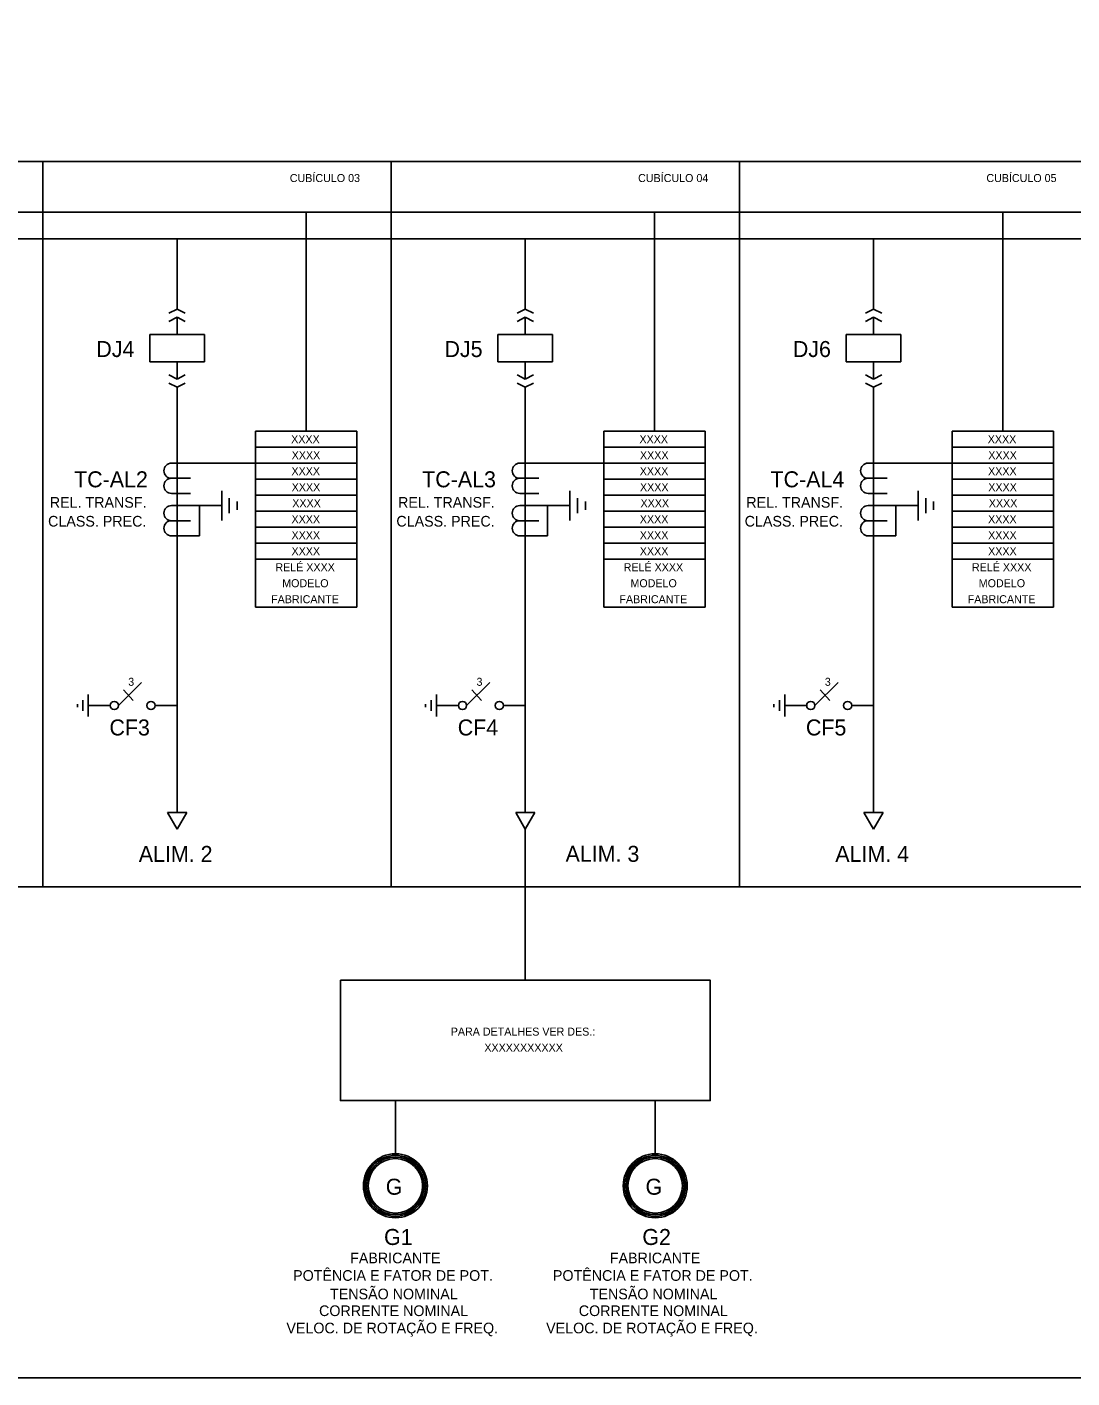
# Model space of a CAD drawing. Extents: x 563 to 1404, y 358 to 952.
# Drawn here: x 837 to 1032.8, y 494.9 to 748.2 of the extents above; entities that cross this region are included whole.
import ezdxf

# ---------------------------------------------------------------- set-up
doc = ezdxf.new("R2010")
doc.units = 0
doc.layers.add('13', color=7, linetype='Continuous')
doc.layers.add('New Level (0)', color=7, linetype='Continuous')

msp = doc.modelspace()

# ---------------------------------------------------------------- linework, layer by layer
for p, q in [((1296.89, 722.95), (622.37, 722.95)), ((839.94, 722.95), (839.94, 586.96)), ((839.94, 722.95), (839.94, 586.96)), ((905.22, 722.95), (905.22, 586.96)), ((905.22, 722.95), (905.22, 586.96)), ((970.5, 722.95), (970.5, 586.96)), ((970.5, 722.95), (970.5, 586.96)), ((1280.96, 713.45), (705.72, 713.45)), ((889.29, 672.38), (889.29, 713.45)), ((954.57, 672.38), (954.57, 713.45)), ((1019.85, 672.38), (1019.85, 713.45)), ((1256.75, 708.46), (681.52, 708.46)), ((865.09, 695.25), (865.09, 708.46)), ((865.09, 695.25), (865.09, 708.46)), ((930.37, 695.25), (930.37, 708.46)), ((930.37, 695.25), (930.37, 708.46)), ((995.64, 695.25), (995.64, 708.46)), ((995.64, 695.25), (995.64, 708.46)), ((865.09, 690.5), (865.09, 693.73)), ((865.09, 690.5), (865.09, 693.73)), ((930.37, 690.5), (930.37, 693.73)), ((930.37, 690.5), (930.37, 693.73)), ((995.64, 690.5), (995.64, 693.73)), ((995.64, 690.5), (995.64, 693.73)), ((859.97, 685.38), (859.97, 690.5)), ((859.97, 690.5), (870.21, 690.5)), ((870.21, 690.5), (870.21, 685.38)), ((925.24, 685.38), (925.24, 690.5)), ((925.24, 690.5), (935.49, 690.5)), ((935.49, 690.5), (935.49, 685.38)), ((990.52, 690.5), (1000.76, 690.5)), ((990.52, 685.38), (990.52, 690.5)), ((1000.76, 690.5), (1000.76, 685.38)), ((870.21, 685.38), (859.97, 685.38)), ((865.09, 685.38), (865.09, 682.16)), ((935.49, 685.38), (925.24, 685.38)), ((930.37, 685.38), (930.37, 682.16)), ((1000.76, 685.38), (990.52, 685.38)), ((995.64, 685.38), (995.64, 682.16)), ((865.09, 600.87), (865.09, 680.63)), ((930.37, 600.87), (930.37, 680.63)), ((995.64, 600.87), (995.64, 680.63)), ((898.78, 672.38), (879.8, 672.38)), ((879.8, 672.38), (879.8, 639.38)), ((898.78, 672.38), (898.78, 639.38)), ((964.06, 672.38), (945.08, 672.38)), ((945.08, 672.38), (945.08, 639.38)), ((964.06, 672.38), (964.06, 639.38)), ((1029.34, 672.38), (1010.36, 672.38)), ((1010.36, 672.38), (1010.36, 639.38)), ((1029.34, 672.38), (1029.34, 639.38)), ((898.78, 669.38), (879.8, 669.38)), ((964.06, 669.38), (945.08, 669.38)), ((1029.34, 669.38), (1010.36, 669.38)), ((864.06, 666.38), (867.6, 666.38)), ((879.8, 666.38), (867.6, 666.38)), ((898.78, 666.38), (879.8, 666.38)), ((929.34, 666.38), (932.88, 666.38)), ((945.08, 666.38), (932.88, 666.38)), ((964.06, 666.38), (945.08, 666.38)), ((994.62, 666.38), (998.16, 666.38)), ((1010.36, 666.38), (998.16, 666.38)), ((1029.34, 666.38), (1010.36, 666.38)), ((864.06, 663.55), (867.6, 663.55)), ((873.47, 661.21), (873.47, 655.63)), ((898.78, 663.38), (879.8, 663.38)), ((929.34, 663.55), (932.88, 663.55)), ((938.74, 661.21), (938.74, 655.63)), ((964.06, 663.38), (945.08, 663.38)), ((994.62, 663.55), (998.16, 663.55)), ((1004.02, 661.21), (1004.02, 655.63)), ((1029.34, 663.38), (1010.36, 663.38)), ((864.06, 660.72), (867.6, 660.72)), ((874.86, 657.02), (874.86, 659.82)), ((876.34, 659.2), (876.34, 657.64)), ((898.78, 660.38), (879.8, 660.38)), ((929.34, 660.72), (932.88, 660.72)), ((940.14, 657.02), (940.14, 659.82)), ((941.62, 659.2), (941.62, 657.64)), ((964.06, 660.38), (945.08, 660.38)), ((994.62, 660.72), (998.16, 660.72)), ((1005.42, 657.02), (1005.42, 659.82)), ((1006.9, 659.2), (1006.9, 657.64)), ((1029.34, 660.38), (1010.36, 660.38)), ((864.06, 658.42), (867.6, 658.42)), ((865.09, 658.42), (873.47, 658.42)), ((898.78, 657.38), (879.8, 657.38)), ((929.34, 658.42), (932.88, 658.42)), ((930.37, 658.42), (938.74, 658.42)), ((964.06, 657.38), (945.08, 657.38)), ((994.62, 658.42), (998.16, 658.42)), ((995.64, 658.42), (1004.02, 658.42)), ((1029.34, 657.38), (1010.36, 657.38)), ((864.06, 655.59), (867.6, 655.59)), ((898.78, 654.38), (879.8, 654.38)), ((898.78, 654.38), (879.8, 654.38)), ((929.34, 655.59), (932.88, 655.59)), ((964.06, 654.38), (945.08, 654.38)), ((964.06, 654.38), (945.08, 654.38)), ((994.62, 655.59), (998.16, 655.59)), ((1029.34, 654.38), (1010.36, 654.38)), ((1029.34, 654.38), (1010.36, 654.38)), ((864.06, 652.76), (869.28, 652.76)), ((898.78, 651.38), (879.8, 651.38)), ((929.34, 652.76), (934.55, 652.76)), ((964.06, 651.38), (945.08, 651.38)), ((994.62, 652.76), (999.83, 652.76)), ((1029.34, 651.38), (1010.36, 651.38)), ((898.78, 648.38), (879.8, 648.38)), ((964.06, 648.38), (945.08, 648.38)), ((1029.34, 648.38), (1010.36, 648.38)), ((898.78, 639.38), (879.8, 639.38)), ((964.06, 639.38), (945.08, 639.38)), ((1029.34, 639.38), (1010.36, 639.38)), ((858.43, 625.29), (854.09, 620.95)), ((855.08, 623.9), (856.87, 621.88)), ((923.7, 625.29), (919.36, 620.95)), ((920.35, 623.9), (922.15, 621.88)), ((988.98, 625.29), (984.64, 620.95)), ((985.63, 623.9), (987.43, 621.88)), ((846.41, 621.19), (846.41, 620.66)), ((847.43, 619.93), (847.43, 621.98)), ((848.45, 623), (848.45, 618.91)), ((852.55, 620.95), (848.45, 620.95)), ((865.09, 620.95), (860.99, 620.95)), ((911.69, 621.19), (911.69, 620.66)), ((912.71, 619.93), (912.71, 621.98)), ((913.73, 623), (913.73, 618.91)), ((917.83, 620.95), (913.73, 620.95)), ((930.37, 620.95), (926.27, 620.95)), ((976.97, 621.19), (976.97, 620.66)), ((977.98, 619.93), (977.98, 621.98)), ((979.01, 623), (979.01, 618.91)), ((983.1, 620.95), (979.01, 620.95)), ((995.64, 620.95), (991.55, 620.95)), ((866.9, 600.87), (863.28, 600.87)), ((863.28, 600.87), (865.09, 597.77)), ((866.9, 600.87), (863.28, 600.87)), ((865.09, 597.77), (866.9, 600.87)), ((932.18, 600.87), (928.56, 600.87)), ((932.18, 600.87), (928.56, 600.87)), ((928.56, 600.87), (930.37, 597.77)), ((930.37, 597.77), (932.18, 600.87)), ((997.45, 600.87), (993.83, 600.87)), ((993.83, 600.87), (995.64, 597.77)), ((997.45, 600.87), (993.83, 600.87)), ((995.64, 597.77), (997.45, 600.87)), ((930.37, 569.44), (930.37, 597.77)), ((1296.89, 586.96), (622.37, 586.96))]:
    msp.add_line(p, q)
for points in [[(906.02, 536.91), (906.02, 546.88)], [(954.71, 536.91), (954.71, 546.88)]]:
    msp.add_lwpolyline(points)
for centre, radius in [((853.32, 620.95), 0.768), ((860.22, 620.95), 0.768), ((918.6, 620.95), 0.768), ((925.5, 620.95), 0.768), ((983.87, 620.95), 0.768), ((990.78, 620.95), 0.768), ((906.02, 530.91), 6), ((906.02, 530.91), 5.7), ((906.02, 530.91), 5.4), ((906.02, 530.91), 5.1), ((954.71, 530.91), 6), ((954.71, 530.91), 5.7), ((954.71, 530.91), 5.4), ((954.71, 530.91), 5.1)]:
    msp.add_circle(centre, radius)
for centre in [(864.06, 664.97), (929.34, 664.97), (994.62, 664.97), (864.06, 662.14), (929.34, 662.14), (994.62, 662.14), (864.06, 657.01), (929.34, 657.01), (994.62, 657.01), (864.06, 654.18), (929.34, 654.18), (994.62, 654.18)]:
    msp.add_arc(centre, 1.42, 90, 270)
at = {"layer": '13'}
for p, q in [((865.09, 695.25), (863.56, 694.49)), ((865.09, 695.25), (866.61, 694.49)), ((930.37, 695.25), (928.84, 694.49)), ((930.37, 695.25), (931.89, 694.49)), ((995.64, 695.25), (994.12, 694.49)), ((995.64, 695.25), (997.17, 694.49)), ((865.09, 693.73), (863.56, 692.97)), ((865.09, 693.73), (866.61, 692.97)), ((930.37, 693.73), (928.84, 692.97)), ((930.37, 693.73), (931.89, 692.97)), ((995.64, 693.73), (994.12, 692.97)), ((995.64, 693.73), (997.17, 692.97)), ((865.09, 682.16), (863.56, 682.92)), ((865.09, 680.63), (863.56, 681.4)), ((865.09, 682.16), (866.61, 682.92)), ((865.09, 680.63), (866.61, 681.4)), ((930.37, 682.16), (928.84, 682.92)), ((930.37, 680.63), (928.84, 681.4)), ((930.37, 682.16), (931.89, 682.92)), ((930.37, 680.63), (931.89, 681.4)), ((995.64, 682.16), (994.12, 682.92)), ((995.64, 680.63), (994.12, 681.4)), ((995.64, 682.16), (997.17, 682.92)), ((995.64, 680.63), (997.17, 681.4))]:
    msp.add_line(p, q, dxfattribs=at)
at = {"layer": 'New Level (0)'}
for p, q in [((869.28, 658.42), (869.28, 652.76)), ((934.55, 658.42), (934.55, 652.76)), ((999.83, 658.42), (999.83, 652.76))]:
    msp.add_line(p, q, dxfattribs=at)
for points in [[(592.61, 760.21), (1379.09, 760.21), (1379.09, 494.89), (592.61, 494.89)], [(895.7, 569.44), (965.03, 569.44), (965.03, 546.88), (895.7, 546.88)]]:
    msp.add_lwpolyline(points, close=True, dxfattribs=at)

# ---------------------------------------------------------------- texts
for s, height, p in [('CUBÍCULO 03', 1.5, (886.23, 719.09)), ('CUBÍCULO 04', 1.5, (951.51, 719.09)), ('CUBÍCULO 05', 1.5, (1016.78, 719.09)), ('DJ4', 3, (849.96, 686.28)), ('DJ5', 3, (915.22, 686.28)), ('DJ6', 3, (980.51, 686.28)), ('XXXX', 1.5, (886.48, 670.13)), ('XXXX', 1.5, (951.76, 670.13)), ('XXXX', 1.5, (1017.04, 670.13)), ('XXXX', 1.5, (886.58, 667.13)), ('XXXX', 1.5, (951.86, 667.13)), ('XXXX', 1.5, (1017.14, 667.13)), ('TC-AL2', 3, (845.8, 661.86)), ('XXXX', 1.5, (886.54, 664.13)), ('TC-AL3', 3, (911.04, 661.86)), ('XXXX', 1.5, (951.82, 664.13)), ('TC-AL4', 3, (976.33, 661.86)), ('XXXX', 1.5, (1017.1, 664.13)), ('XXXX', 1.5, (886.58, 661.13)), ('XXXX', 1.5, (951.86, 661.13)), ('XXXX', 1.5, (1017.14, 661.13)), ('REL. TRANSF.', 2, (841.24, 658.04)), ('XXXX', 1.5, (886.69, 658.13)), ('REL. TRANSF.', 2, (906.51, 658.04)), ('XXXX', 1.5, (951.96, 658.13)), ('REL. TRANSF.', 2, (971.79, 658.04)), ('XXXX', 1.5, (1017.24, 658.13)), ('CLASS. PREC.', 2, (840.92, 654.5)), ('XXXX', 1.5, (886.55, 655.13)), ('CLASS. PREC.', 2, (906.2, 654.5)), ('XXXX', 1.5, (951.83, 655.13)), ('CLASS. PREC.', 2, (971.48, 654.5)), ('XXXX', 1.5, (1017.1, 655.13)), ('XXXX', 1.5, (886.55, 652.13)), ('XXXX', 1.5, (951.83, 652.13)), ('XXXX', 1.5, (1017.11, 652.13)), ('XXXX', 1.5, (886.55, 649.13)), ('XXXX', 1.5, (951.83, 649.13)), ('XXXX', 1.5, (1017.11, 649.13)), ('RELÉ XXXX', 1.5, (883.52, 646.13)), ('RELÉ XXXX', 1.5, (948.8, 646.13)), ('RELÉ XXXX', 1.5, (1014.08, 646.13)), ('MODELO', 1.5, (884.8, 643.13)), ('MODELO', 1.5, (950.07, 643.13)), ('MODELO', 1.5, (1015.35, 643.13)), ('FABRICANTE', 1.5, (882.72, 640.13)), ('FABRICANTE', 1.5, (948, 640.13)), ('FABRICANTE', 1.5, (1013.28, 640.13)), ('3', 1.5, (855.94, 624.65)), ('3', 1.5, (921.22, 624.65)), ('3', 1.5, (986.5, 624.65)), ('CF3', 3, (852.42, 615.34)), ('CF4', 3, (917.7, 615.34)), ('CF5', 3, (982.96, 615.34)), ('ALIM. 2', 3, (857.92, 591.63)), ('ALIM. 3', 3, (937.91, 591.65)), ('ALIM. 4', 3, (988.47, 591.64)), ('PARA DETALHES VER DES.:', 1.5, (916.39, 559.07)), ('XXXXXXXXXXX', 1.5, (922.69, 556.07)), ('G', 3, (904.21, 529.24)), ('G', 3, (952.9, 529.24)), ('G1', 3, (903.89, 519.82)), ('G2', 3, (952.3, 519.82)), ('FABRICANTE', 2, (897.53, 516.38)), ('FABRICANTE', 2, (946.21, 516.38)), ('POTÊNCIA E FATOR DE POT.', 2, (886.85, 513.1)), ('POTÊNCIA E FATOR DE POT.', 2, (935.54, 513.1)), ('TENSÃO NOMINAL', 2, (893.77, 509.63)), ('TENSÃO NOMINAL', 2, (942.45, 509.63)), ('CORRENTE NOMINAL', 2, (891.71, 506.49)), ('CORRENTE NOMINAL', 2, (940.39, 506.49)), ('VELOC. DE ROTAÇÃO E FREQ.', 2, (885.59, 503.25)), ('VELOC. DE ROTAÇÃO E FREQ.', 2, (934.27, 503.25))]:
    msp.add_text(s, height=height).set_placement(p)

doc.saveas('drawing.dxf')
